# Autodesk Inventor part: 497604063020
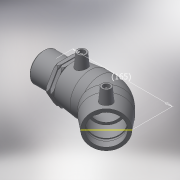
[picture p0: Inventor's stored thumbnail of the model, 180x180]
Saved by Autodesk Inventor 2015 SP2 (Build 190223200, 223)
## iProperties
Created: 2017-06
Part Number: 497604063020
Material: Generic
Description: PLASSON PE MALE TRANSITION 45° ELBOW 63-2"
Document SubType Name: Modeling
Designer: KIM
Mass: 55.0731 g
Surface Area: 148.067 cm^2
Volume: 55.0731 cm^3
Density: 1 g/cm^3
Appearance: Default
Author: KIM
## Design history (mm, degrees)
derived "497604.ipt"
feature "Solid1::497604.ipt"
tag "TaggingFeature1"
body "Solid1"
other parameters: "d2" = 82, "d4" = 34.75, "d5" = 73.8, "d8" = 168 deg, "d11" = 6.66667, "d29" = 59, "d30" = 15, "d31" = 48.65, "d34" = 5 deg, "d41" = 4, "d42" = 14, "d43" = 0, "d49" = 63, "d50" = 53.55, "d52" = 49.9, "d54" = 135 deg, "d86" = 36.9, "d87" = 135 deg, "d88" = 139, "d91" = 0, "d93" = 0, "d101" = 3, "d102" = 0, "d107" = 0.1, "d108" = 48, "d109" = 59.614, "d110" = 57, "d111" = 14.25, "d112" = 82, "d113" = 41.7298, "d114" = 51.3, "d116" = 2.46, "d122" = 0, "d123" = 2.9807, "d126" = 1.425, "d127" = 6.4125, "d128" = 82, "d131" = 63, "d_" = 63, "L_" = 196, "D_" = 48, "A_" = 59, "d_2" = 12, "L_1" = 57, "R_" = 59.614, "D_1" = 82, "d129" = 196
